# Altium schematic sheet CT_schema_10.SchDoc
size 274 x 160 mm
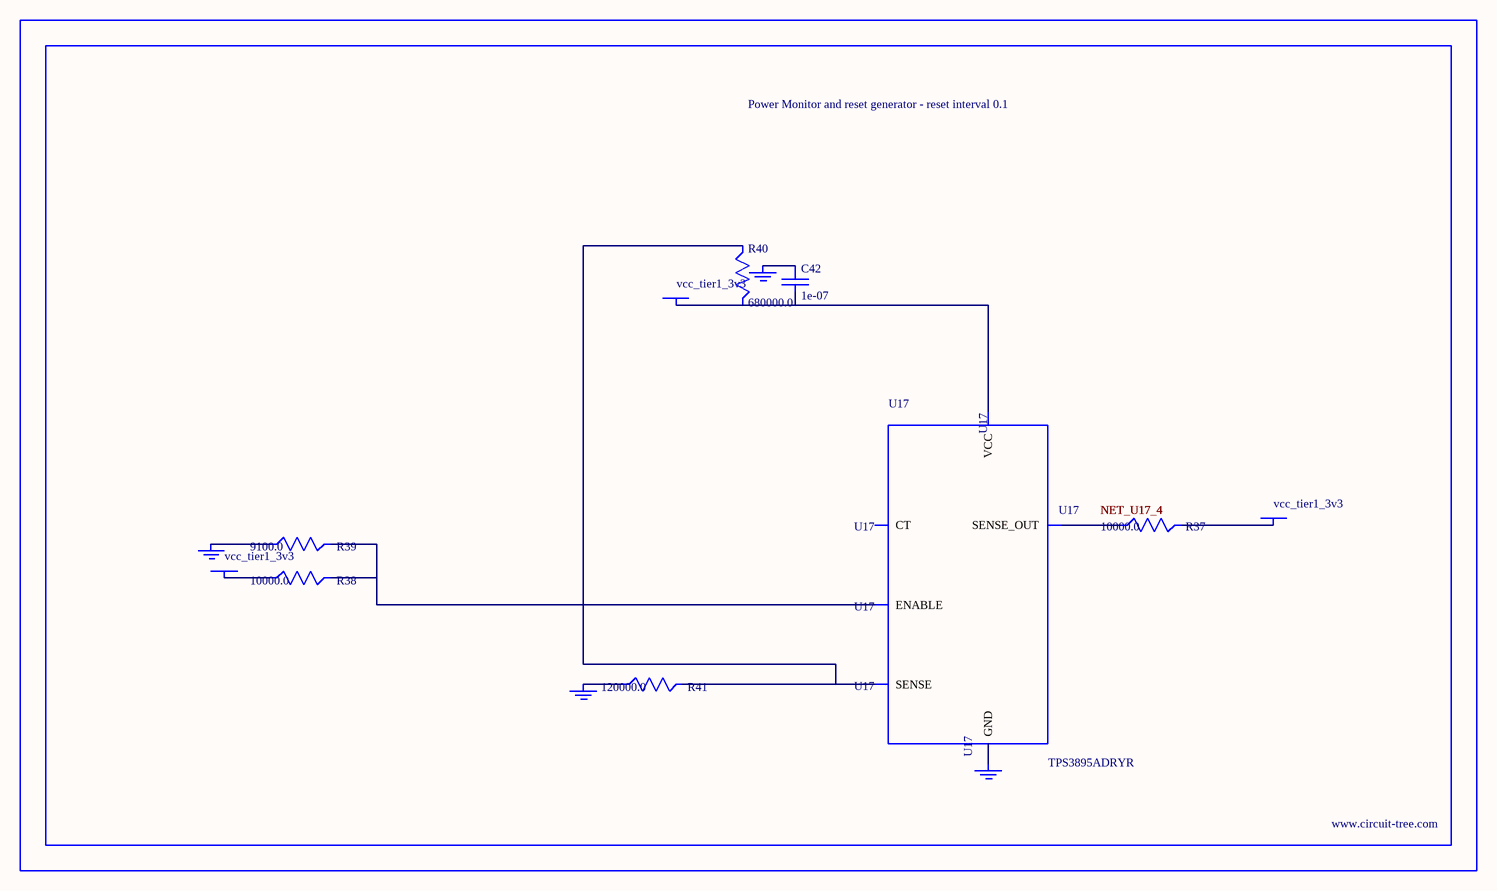
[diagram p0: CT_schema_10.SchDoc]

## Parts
BORDER9  (no value)
C42  1e-07  [C0402]
GND_INSTANCE_9_0  (no value)
GND_INSTANCE_9_1  (no value)
GND_INSTANCE_9_2  (no value)
GND_INSTANCE_9_3  (no value)
POWER_INSTANCE_9_0  vcc_tier1_3v3
POWER_INSTANCE_9_1  vcc_tier1_3v3
POWER_INSTANCE_9_2  vcc_tier1_3v3
R37  10000.0  [R0603]
R38  10000.0  [R0603]
R39  9100.0  [R0603]
R40  680000.0  [R0603]
R41  120000.0  [R0603]
U17  TPS3895ADRYR  [SON-6]

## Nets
NetC42_1: C42.1 GND_INSTANCE_9_2.0(GND)
NetC42_2: C42.2 POWER_INSTANCE_9_2.0(PWR) R40.2 U17.6(VCC)
NetGND_INSTANCE_9_0_0: GND_INSTANCE_9_0.0(GND) R39.1
NetGND_INSTANCE_9_1_0: GND_INSTANCE_9_1.0(GND) R41.1
NetGND_INSTANCE_9_3_0: GND_INSTANCE_9_3.0(GND) U17.2(GND)
NetPOWER_INSTANCE_9_0_0: POWER_INSTANCE_9_0.0(PWR) R38.1
NetPOWER_INSTANCE_9_1_0: POWER_INSTANCE_9_1.0(PWR) R37.2
NetR37_1: R37.1 U17.4(SENSE_OUT)
NetR38_2: R38.2 R39.2 U17.1(ENABLE)
NetR40_1: R40.1 R41.2 U17.3(SENSE)

Not connected (* = marked no-connect by the designer): U17 5(CT)

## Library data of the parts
BORDER9 = BORDER_PAGE9
C42 = C0402C104K3RACTU
GND_INSTANCE_9_0-GND_INSTANCE_9_3 = GND
POWER_INSTANCE_9_0-POWER_INSTANCE_9_2 = PWR
R37 R38 = RC0603JR-0710KL
R39 = RC0603JR-079K1L
R40 = RC0603JR-07680KL
R41 = RC0603JR-07120KL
